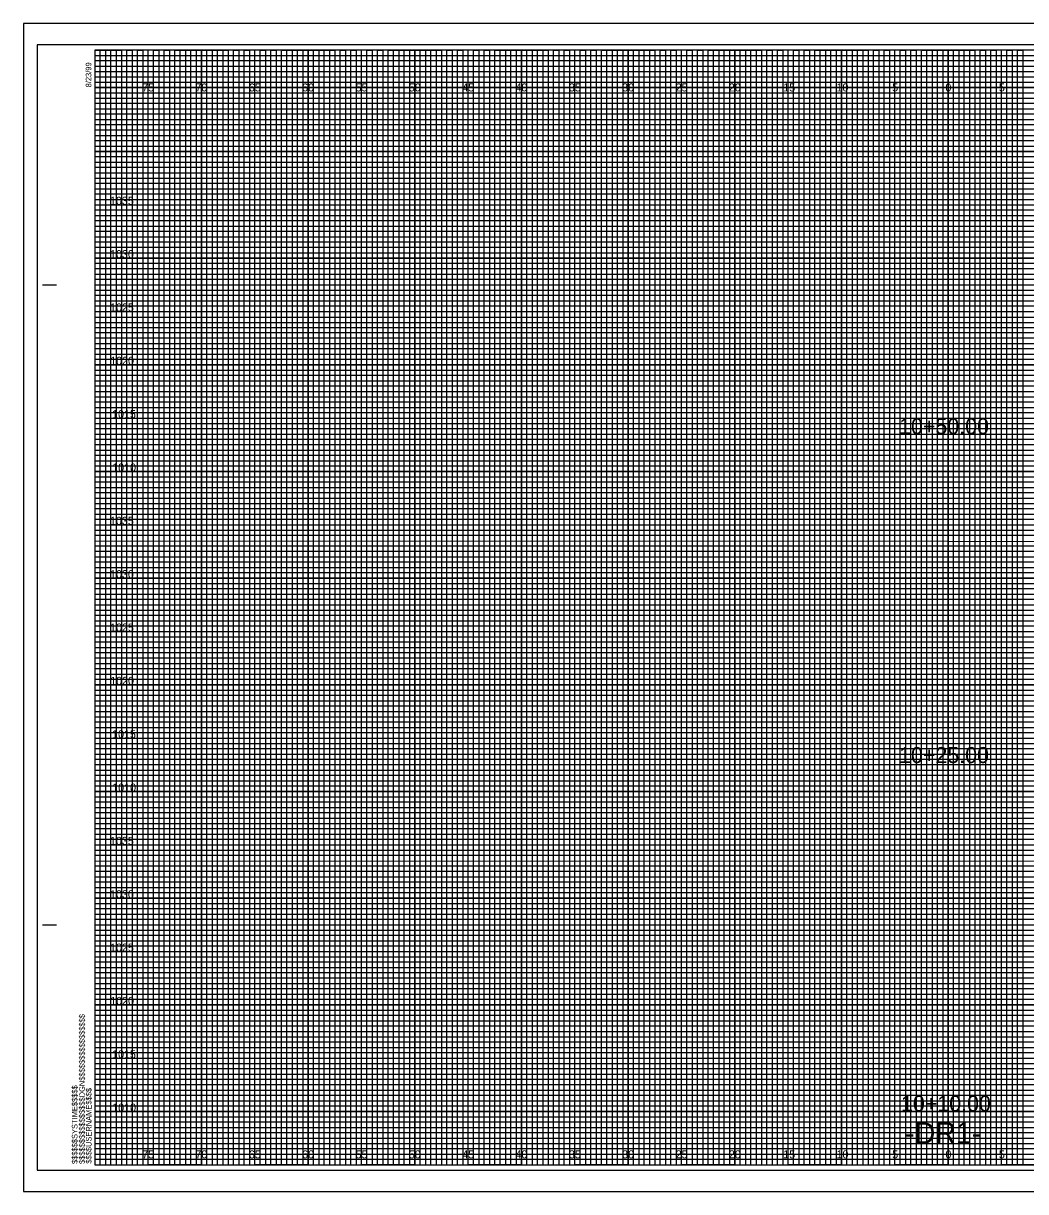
# Model space of a CAD drawing. Extents: x -7 to 180, y -2 to 107.
# Drawn here: x -6.7 to 87.2, y -2.5 to 107 of the extents above; entities that cross this region are included whole.
import ezdxf

# ---------------------------------------------------------------- set-up
doc = ezdxf.new("R2010")
doc.units = 0
for name, color, linetype in [('Exist Cross Section Cell', 7, 'Continuous'), ('Exist XS Center Line Elevation Label', 7, 'Continuous'), ('Exist XS Ground Line', 7, 'Continuous'), ('Prop CMT Concrete Structures', 7, 'Continuous'), ('Prop CMT DNC', 7, 'Continuous'), ('Prop CMT Guardrail Widen Shoulder', 7, 'Continuous'), ('Prop CMT Pvmt Course 1', 7, 'Continuous'), ('Prop CMT Pvmt Surface', 7, 'Continuous'), ('Prop CMT Shld Paved Course 1', 7, 'Continuous'), ('Prop CMT Slope Grass', 7, 'Continuous'), ('Prop CMT Subgrade Earthwork', 7, 'Continuous'), ('Prop XS Side Slope Text', 7, 'Continuous'), ('Typical Text Label CELL', 7, 'Continuous')]:
    doc.layers.add(name, color=color, linetype=linetype)

msp = doc.modelspace()

# ---------------------------------------------------------------- linework, layer by layer
at = {"layer": 'Exist XS Center Line Elevation Label'}
for points in [[(0, 104.5), (2.5, 104.5), (2.5, 0), (7.5, 0), (7.5, 104.5), (12.5, 104.5), (12.5, 0), (17.5, 0), (17.5, 104.5), (22.5, 104.5), (22.5, 0), (27.5, 0), (27.5, 104.5), (32.5, 104.5), (32.5, 0), (37.5, 0), (37.5, 104.5), (42.5, 104.5), (42.5, 0), (47.5, 0), (47.5, 104.5), (52.5, 104.5), (52.5, 0), (57.5, 0), (57.5, 104.5), (62.5, 104.5), (62.5, 0), (67.5, 0), (67.5, 104.5), (72.5, 104.5), (72.5, 0), (77.5, 0), (77.5, 104.5), (82.5, 104.5), (82.5, 0), (87.5, 0)], [(0, 102), (137.5, 102)], [(0, 92.5), (160, 92.5), (160, 97.5), (0, 97.5)], [(0, 82.5), (160, 82.5), (160, 87.5), (0, 87.5)], [(0, 72.5), (160, 72.5), (160, 77.5), (0, 77.5)], [(0, 62.5), (160, 62.5), (160, 67.5), (0, 67.5)], [(0, 52.5), (160, 52.5), (160, 57.5), (0, 57.5)], [(0, 42.5), (160, 42.5), (160, 47.5), (0, 47.5)], [(0, 32.5), (160, 32.5), (160, 37.5), (0, 37.5)], [(0, 22.5), (160, 22.5), (160, 27.5), (0, 27.5)], [(0, 12.5), (160, 12.5), (160, 17.5), (0, 17.5)], [(0, 2.5), (160, 2.5), (160, 7.5), (0, 7.5)]]:
    msp.add_lwpolyline(points, dxfattribs=at)
at = {"layer": 'Exist XS Ground Line'}
for p, q in [((5, 104.5), (0, 104.5)), ((5, 0), (5, 104.5)), ((15, 104.5), (10, 104.5)), ((10, 104.5), (10, 0)), ((15, 0), (15, 104.5)), ((25, 104.5), (20, 104.5)), ((20, 104.5), (20, 0)), ((25, 0), (25, 104.5)), ((35, 104.5), (30, 104.5)), ((30, 104.5), (30, 0)), ((35, 0), (35, 104.5)), ((45, 104.5), (40, 104.5)), ((40, 104.5), (40, 0)), ((45, 0), (45, 104.5)), ((55, 104.5), (50, 104.5)), ((50, 104.5), (50, 0)), ((55, 0), (55, 104.5)), ((65, 104.5), (60, 104.5)), ((60, 104.5), (60, 0)), ((65, 0), (65, 104.5)), ((75, 104.5), (70, 104.5)), ((70, 104.5), (70, 0)), ((75, 0), (75, 104.5)), ((85, 104.5), (80, 104.5)), ((80, 104.5), (80, 0)), ((85, 0), (85, 104.5)), ((10, 0), (5, 0)), ((20, 0), (15, 0)), ((30, 0), (25, 0)), ((40, 0), (35, 0)), ((50, 0), (45, 0)), ((60, 0), (55, 0)), ((70, 0), (65, 0)), ((80, 0), (75, 0)), ((90, 0), (85, 0))]:
    msp.add_line(p, q, dxfattribs=at)
for points in [[(0, 100), (160, 100), (160, 95), (0, 95)], [(0, 90), (160, 90), (160, 85), (0, 85)], [(0, 80), (160, 80), (160, 75), (0, 75)], [(0, 70), (160, 70), (160, 65), (0, 65)], [(0, 60), (160, 60), (160, 55), (0, 55)], [(0, 50), (160, 50), (160, 45), (0, 45)], [(0, 40), (160, 40), (160, 35), (0, 35)], [(0, 30), (160, 30), (160, 25), (0, 25)], [(0, 20), (160, 20), (160, 15), (0, 15)], [(0, 10), (160, 10), (160, 5), (0, 5)]]:
    msp.add_lwpolyline(points, dxfattribs=at)
at = {"layer": 'Prop CMT Concrete Structures'}
for p, q in [((5, 0), (5, 104.5)), ((10, 0), (10, 104.5)), ((15, 0), (15, 104.5)), ((20, 0), (20, 104.5)), ((25, 0), (25, 104.5)), ((30, 0), (30, 104.5)), ((35, 0), (35, 104.5)), ((40, 0), (40, 104.5)), ((45, 0), (45, 104.5)), ((50, 0), (50, 104.5)), ((55, 0), (55, 104.5)), ((60, 0), (60, 104.5)), ((65, 0), (65, 104.5)), ((70, 0), (70, 104.5)), ((75, 0), (75, 104.5)), ((80, 0), (80, 104.5)), ((85, 0), (85, 104.5)), ((0, 100), (160, 100)), ((0, 95), (160, 95)), ((0, 90), (160, 90)), ((0, 85), (160, 85)), ((0, 80), (160, 80)), ((0, 75), (160, 75)), ((0, 70), (160, 70)), ((0, 65), (160, 65)), ((0, 60), (160, 60)), ((0, 55), (160, 55)), ((0, 50), (160, 50)), ((0, 45), (160, 45)), ((0, 40), (160, 40)), ((0, 35), (160, 35)), ((0, 30), (160, 30)), ((0, 25), (160, 25)), ((0, 20), (160, 20)), ((0, 15), (160, 15)), ((0, 10), (160, 10)), ((0, 5), (160, 5))]:
    msp.add_line(p, q, dxfattribs=at)
at = {"layer": 'Prop CMT Guardrail Widen Shoulder'}
for p, q in [((161.65, 107), (-6.7, 107)), ((-6.7, 107), (-6.7, -2.5)), ((-6.7, -2.5), (161.65, -2.5))]:
    msp.add_line(p, q, dxfattribs=at)
at = {"layer": 'Prop CMT Pvmt Course 1'}
msp.add_lwpolyline([(-6.7, -2.5), (161.65, -2.5), (161.65, 107), (-6.7, 107)], close=True, dxfattribs=at)
at = {"layer": 'Prop CMT Pvmt Surface'}
for points in [[(0, 0), (0.5, 0), (0.5, 104.5), (1, 104.5), (1, 0)], [(1, 0), (1.5, 0), (1.5, 104.5), (2, 104.5), (2, 0)], [(2.5, 0), (3, 0), (3, 104.5), (3.5, 104.5), (3.5, 0)], [(3.5, 0), (4, 0), (4, 104.5), (4.5, 104.5), (4.5, 0)], [(5, 0), (5.5, 0), (5.5, 104.5), (6, 104.5), (6, 0)], [(6, 0), (6.5, 0), (6.5, 104.5), (7, 104.5), (7, 0)], [(7.5, 0), (8, 0), (8, 104.5), (8.5, 104.5), (8.5, 0)], [(8.5, 0), (9, 0), (9, 104.5), (9.5, 104.5), (9.5, 0)], [(10, 0), (10.5, 0), (10.5, 104.5), (11, 104.5), (11, 0)], [(11, 0), (11.5, 0), (11.5, 104.5), (12, 104.5), (12, 0)], [(12.5, 0), (13, 0), (13, 104.5), (13.5, 104.5), (13.5, 0)], [(13.5, 0), (14, 0), (14, 104.5), (14.5, 104.5), (14.5, 0)], [(15, 0), (15.5, 0), (15.5, 104.5), (16, 104.5), (16, 0)], [(16, 0), (16.5, 0), (16.5, 104.5), (17, 104.5), (17, 0)], [(17.5, 0), (18, 0), (18, 104.5), (18.5, 104.5), (18.5, 0)], [(18.5, 0), (19, 0), (19, 104.5), (19.5, 104.5), (19.5, 0)], [(20, 0), (20.5, 0), (20.5, 104.5), (21, 104.5), (21, 0)], [(21, 0), (21.5, 0), (21.5, 104.5), (22, 104.5), (22, 0)], [(22.5, 0), (23, 0), (23, 104.5), (23.5, 104.5), (23.5, 0)], [(23.5, 0), (24, 0), (24, 104.5), (24.5, 104.5), (24.5, 0)], [(25, 0), (25.5, 0), (25.5, 104.5), (26, 104.5), (26, 0)], [(26, 0), (26.5, 0), (26.5, 104.5), (27, 104.5), (27, 0)], [(27.5, 0), (28, 0), (28, 104.5), (28.5, 104.5), (28.5, 0)], [(28.5, 0), (29, 0), (29, 104.5), (29.5, 104.5), (29.5, 0)], [(30, 0), (30.5, 0), (30.5, 104.5), (31, 104.5), (31, 0)], [(31, 0), (31.5, 0), (31.5, 104.5), (32, 104.5), (32, 0)], [(32.5, 0), (33, 0), (33, 104.5), (33.5, 104.5), (33.5, 0)], [(33.5, 0), (34, 0), (34, 104.5), (34.5, 104.5), (34.5, 0)], [(35, 0), (35.5, 0), (35.5, 104.5), (36, 104.5), (36, 0)], [(36, 0), (36.5, 0), (36.5, 104.5), (37, 104.5), (37, 0)], [(37.5, 0), (38, 0), (38, 104.5), (38.5, 104.5), (38.5, 0)], [(38.5, 0), (39, 0), (39, 104.5), (39.5, 104.5), (39.5, 0)], [(40, 0), (40.5, 0), (40.5, 104.5), (41, 104.5), (41, 0)], [(41, 0), (41.5, 0), (41.5, 104.5), (42, 104.5), (42, 0)], [(42.5, 0), (43, 0), (43, 104.5), (43.5, 104.5), (43.5, 0)], [(43.5, 0), (44, 0), (44, 104.5), (44.5, 104.5), (44.5, 0)], [(45, 0), (45.5, 0), (45.5, 104.5), (46, 104.5), (46, 0)], [(46, 0), (46.5, 0), (46.5, 104.5), (47, 104.5), (47, 0)], [(47.5, 0), (48, 0), (48, 104.5), (48.5, 104.5), (48.5, 0)], [(48.5, 0), (49, 0), (49, 104.5), (49.5, 104.5), (49.5, 0)], [(50, 0), (50.5, 0), (50.5, 104.5), (51, 104.5), (51, 0)], [(51, 0), (51.5, 0), (51.5, 104.5), (52, 104.5), (52, 0)], [(52.5, 0), (53, 0), (53, 104.5), (53.5, 104.5), (53.5, 0)], [(53.5, 0), (54, 0), (54, 104.5), (54.5, 104.5), (54.5, 0)], [(55, 0), (55.5, 0), (55.5, 104.5), (56, 104.5), (56, 0)], [(56, 0), (56.5, 0), (56.5, 104.5), (57, 104.5), (57, 0)], [(57.5, 0), (58, 0), (58, 104.5), (58.5, 104.5), (58.5, 0)], [(58.5, 0), (59, 0), (59, 104.5), (59.5, 104.5), (59.5, 0)], [(60, 0), (60.5, 0), (60.5, 104.5), (61, 104.5), (61, 0)], [(61, 0), (61.5, 0), (61.5, 104.5), (62, 104.5), (62, 0)], [(62.5, 0), (63, 0), (63, 104.5), (63.5, 104.5), (63.5, 0)], [(63.5, 0), (64, 0), (64, 104.5), (64.5, 104.5), (64.5, 0)], [(65, 0), (65.5, 0), (65.5, 104.5), (66, 104.5), (66, 0)], [(66, 0), (66.5, 0), (66.5, 104.5), (67, 104.5), (67, 0)], [(67.5, 0), (68, 0), (68, 104.5), (68.5, 104.5), (68.5, 0)], [(68.5, 0), (69, 0), (69, 104.5), (69.5, 104.5), (69.5, 0)], [(70, 0), (70.5, 0), (70.5, 104.5), (71, 104.5), (71, 0)], [(71, 0), (71.5, 0), (71.5, 104.5), (72, 104.5), (72, 0)], [(72.5, 0), (73, 0), (73, 104.5), (73.5, 104.5), (73.5, 0)], [(73.5, 0), (74, 0), (74, 104.5), (74.5, 104.5), (74.5, 0)], [(75, 0), (75.5, 0), (75.5, 104.5), (76, 104.5), (76, 0)], [(76, 0), (76.5, 0), (76.5, 104.5), (77, 104.5), (77, 0)], [(77.5, 0), (78, 0), (78, 104.5), (78.5, 104.5), (78.5, 0)], [(78.5, 0), (79, 0), (79, 104.5), (79.5, 104.5), (79.5, 0)], [(80, 0), (80.5, 0), (80.5, 104.5), (81, 104.5), (81, 0)], [(81, 0), (81.5, 0), (81.5, 104.5), (82, 104.5), (82, 0)], [(82.5, 0), (83, 0), (83, 104.5), (83.5, 104.5), (83.5, 0)], [(83.5, 0), (84, 0), (84, 104.5), (84.5, 104.5), (84.5, 0)], [(85, 0), (85.5, 0), (85.5, 104.5), (86, 104.5), (86, 0)], [(86, 0), (86.5, 0), (86.5, 104.5), (87, 104.5), (87, 0)]]:
    msp.add_lwpolyline(points, dxfattribs=at)
at = {"layer": 'Prop CMT Shld Paved Course 1'}
for p, q in [((0, 104), (130, 104)), ((130, 103.49), (0, 103.49)), ((0, 103.49), (0, 103)), ((0, 103), (130, 103)), ((130, 102.45), (0, 102.45)), ((0, 102.45), (0, 101.5)), ((0, 101.5), (160, 101.5))]:
    msp.add_line(p, q, dxfattribs=at)
for points in [[(0, 101), (135, 101), (160, 101), (160, 101), (0, 101)], [(0, 100.5), (160, 100.5), (160, 99.5), (0, 99.5)], [(0, 99), (160, 99), (160, 98.5), (0, 98.49)], [(0, 98), (160, 98), (160, 97), (0, 97)], [(0, 96.5), (160, 96.5), (160, 96), (0, 96)], [(0, 95.5), (160, 95.5), (160, 94.5), (0, 94.5)], [(0, 94), (160, 94), (160, 93.5), (0, 93.5)], [(0, 93), (160, 93), (160, 92), (0, 92)], [(0, 91.5), (160, 91.5), (160, 91), (0, 91)], [(0, 90.5), (160, 90.5), (160, 89.5), (0, 89.5)], [(0, 89), (160, 89), (160, 88.5), (0, 88.5)], [(0, 88), (160, 88), (160, 86.98), (160, 86.5), (160, 86), (0, 86)], [(0, 87), (160, 87), (160, 86.5), (0, 86.5)], [(0, 85.5), (160, 85.5), (160, 84.5), (0, 84.52)], [(0, 84.52), (160, 84.5), (160, 84), (0, 84)], [(0, 83.5), (160, 83.5), (160, 83), (0, 83)], [(0, 82), (160, 82), (160, 81.5), (0, 81.5)], [(0, 81), (160, 81), (160, 80.5), (0, 80.5)], [(-0.04, 79.45), (160, 79.45), (160, 78.94), (-0.04, 78.94)], [(0, 78.5), (160, 78.5), (160, 78), (0, 78)], [(0, 77), (160, 77), (160, 76.5), (0, 76.5)], [(0, 76), (160, 76), (160, 75.5), (0, 75.5)], [(0, 74.5), (160, 74.5), (160, 74), (0, 74)], [(0, 73.5), (160, 73.5), (160, 73), (0, 73)], [(0, 72), (160, 72), (160, 71.5), (0, 71.5)], [(0, 71), (160, 71), (160, 70.5), (0, 70.5)], [(0, 69.5), (160, 69.5), (160, 68.99), (0, 69)], [(0, 68.5), (160, 68.5), (160, 68), (0, 68)], [(0, 67), (160, 67), (160, 66.5), (0, 66.5)], [(0, 66), (160, 66), (160, 65.5), (0, 65.5)], [(0, 64.5), (160, 64.5), (160, 64), (0, 64)], [(0, 63.5), (160, 63.5), (160, 63), (0, 63)], [(0, 62), (160, 62), (160, 61.5), (0, 61.5)], [(0, 61), (160, 61), (160, 60.5), (0, 60.5)], [(0, 59.5), (160, 59.5), (160, 59), (0, 59)], [(0, 58.5), (160.03, 58.45), (160, 58), (0, 58)], [(0, 57), (160, 57), (160, 56.5), (0, 56.5)], [(0, 56), (160, 56), (160, 55.5), (0, 55.5)], [(0, 54.5), (160, 54.5), (160, 54), (0, 54)], [(0, 53.5), (160, 53.5), (160, 53), (0, 53)], [(0, 52), (160, 52), (160, 51.5), (0, 51.5)], [(0, 51), (160, 51), (160, 50.5), (0, 50.5)], [(0, 49.5), (160, 49.5), (160, 49), (0, 49)], [(0, 48.5), (160, 48.5), (160, 48), (0, 48)], [(0, 47), (160, 47), (160, 46.5), (0, 46.5)], [(0, 46), (160, 46), (160, 45.5), (0, 45.5)], [(0, 44.5), (160, 44.5), (160, 44), (0, 44)], [(0, 43.5), (160, 43.5), (160, 43), (0, 43)], [(0, 42), (160, 42), (160, 41.5), (0, 41.5)], [(0, 41), (160, 41), (160, 40.5), (0, 40.5)], [(0, 39.5), (160, 39.5), (160, 38.99), (0, 39)], [(0, 38.5), (160, 38.5), (160, 38), (0, 38)], [(0, 37), (160, 37), (160, 36.5), (0, 36.5)], [(0, 36), (160, 36), (160, 35.5), (0, 35.5)], [(0, 34.5), (160, 34.5), (160, 34), (0, 34)], [(0, 33.5), (160, 33.5), (160, 33), (0, 33)], [(0, 32), (160, 32), (160, 31.5), (0, 31.5)], [(0, 31), (160, 31), (160, 30.5), (0, 30.5)], [(0, 29.5), (160, 29.5), (160, 29), (0, 29)], [(0, 28.5), (160.03, 28.46), (160, 28), (0, 28)], [(0, 27), (160, 27), (160, 26.5), (0, 26.5)], [(0, 26), (160, 26), (160, 25.5), (0, 25.5)], [(0, 24.5), (160, 24.5), (160, 24), (0, 24)], [(0, 23.5), (160, 23.5), (160, 23), (0, 23)], [(0, 22), (160, 22), (160, 21.5), (0, 21.5)], [(0, 21), (160, 21), (160, 20.5), (0, 20.5)], [(0, 19.5), (160, 19.5), (160, 19), (0, 19)], [(0, 18.5), (160, 18.5), (160, 18), (0, 18)], [(0, 17), (160, 17), (160, 16.5), (0, 16.5)], [(0, 16), (160, 16), (160, 15.5), (0, 15.5)], [(0, 14.5), (160, 14.5), (160, 14), (0, 14)], [(0, 13.5), (160, 13.5), (160, 13), (0, 13)], [(0, 12), (160, 12), (160, 11.5), (0, 11.5)], [(0, 11), (160, 11), (160, 10.5), (0, 10.5)], [(0, 9.5), (160, 9.5), (160, 9), (0, 9)], [(0, 8.5), (160, 8.5), (160, 8), (0, 8)], [(0, 7), (160, 7), (160, 6.5), (0, 6.5)], [(0, 6), (160, 6), (160, 5.5), (0, 5.5)], [(0, 4.5), (160, 4.5), (160, 4), (0, 4)], [(0, 3.5), (160, 3.5), (160, 3), (0, 3)], [(0, 2), (160, 2), (160, 1.5), (0, 1.5)], [(0, 1), (160, 1), (160, 0.5), (0, 0.5)]]:
    msp.add_lwpolyline(points, dxfattribs=at)
at = {"layer": 'Prop CMT Slope Grass'}
msp.add_lwpolyline([(-5.4, -0.5), (161.2, -0.5), (161.2, 105), (-5.4, 105)], close=True, dxfattribs=at)
at = {"layer": 'Prop CMT Subgrade Earthwork'}
for p, q in [((-4.9, 82.5), (-3.65, 82.5)), ((-4.85, 82.5), (-3.6, 82.5)), ((-4.9, 22.5), (-3.65, 22.5)), ((-4.85, 22.5), (-3.6, 22.5)), ((0, 0), (0, 0)), ((0, 0), (0, 0)), ((0, 0), (0, 0)), ((0, 0), (0, 0)), ((0, 0), (0, 0)), ((0, 0), (0, 0)), ((0, 0), (0, 0))]:
    msp.add_line(p, q, dxfattribs=at)
msp.add_lwpolyline([(160, 104.5), (0, 104.5), (0, 0), (160, 0)], close=True, dxfattribs=at)

# ---------------------------------------------------------------- texts
at = {"layer": 'Exist Cross Section Cell'}
for s, p in [('75', (4.44, 100.62)), ('70', (9.43, 100.62)), ('65', (14.44, 100.62)), ('60', (19.43, 100.62)), ('55', (24.44, 100.62)), ('50', (29.43, 100.62)), ('45', (34.44, 100.62)), ('40', (39.43, 100.62)), ('35', (44.44, 100.62)), ('30', (49.43, 100.62)), ('25', (54.44, 100.62)), ('20', (59.43, 100.62)), ('15', (64.53, 100.62)), ('10', (69.52, 100.62)), ('5', (74.74, 100.62)), ('0', (79.73, 100.62)), ('0', (79.73, 100.62)), ('5', (84.74, 100.62)), ('75', (4.44, 0.62)), ('70', (9.43, 0.62)), ('65', (14.44, 0.62)), ('60', (19.43, 0.62)), ('55', (24.44, 0.62)), ('50', (29.43, 0.62)), ('45', (34.44, 0.62)), ('40', (39.43, 0.62)), ('35', (44.44, 0.62)), ('30', (49.43, 0.62)), ('25', (54.44, 0.62)), ('20', (59.43, 0.62)), ('15', (64.53, 0.62)), ('10', (69.52, 0.62)), ('5', (74.74, 0.62)), ('0', (79.73, 0.62)), ('0', (79.73, 0.62)), ('5', (84.74, 0.62))]:
    msp.add_text(s, height=0.75, dxfattribs=at).set_placement(p)
at = {"layer": 'Prop CMT DNC'}
msp.add_text('-DR1-', height=2, dxfattribs=at).set_placement((75.96, 2))
at = {"layer": 'Prop CMT Subgrade Earthwork'}
for s, p in [('8/23/99', (-0.33, 101)), ('$$$$$$$$$$$$$$$$DGN$$$$$$$$$$$$$$$$', (-0.94, 0.09)), ('$$$$$$SYSTIME$$$$$', (-1.63, 0.09)), ('$$$$USERNAME$$$$', (-0.31, 0.12))]:
    msp.add_text(s, height=0.525, rotation=90, dxfattribs=at).set_placement(p)
at = {"layer": 'Prop XS Side Slope Text'}
for s, p in [('10+50.00', (75.39, 68.49)), ('10+25.00', (75.39, 37.67)), ('10+10.00', (75.57, 5.01))]:
    msp.add_text(s, height=1.5, dxfattribs=at).set_placement(p)
at = {"layer": 'Typical Text Label CELL'}
for s, p in [('1035', (1.42, 90)), ('1030', (1.43, 85)), ('1025', (1.43, 80)), ('1020', (1.44, 75)), ('1015', (1.62, 70)), ('1010', (1.63, 65)), ('1035', (1.42, 60)), ('1030', (1.43, 55)), ('1025', (1.43, 50)), ('1020', (1.44, 45)), ('1015', (1.62, 40)), ('1010', (1.63, 35)), ('1035', (1.42, 30)), ('1030', (1.43, 25)), ('1025', (1.43, 20)), ('1020', (1.44, 15)), ('1015', (1.62, 10)), ('1010', (1.63, 5))]:
    msp.add_text(s, height=0.75, dxfattribs=at).set_placement(p)

doc.saveas('drawing.dxf')
